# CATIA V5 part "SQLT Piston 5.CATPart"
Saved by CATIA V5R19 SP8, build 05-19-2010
Part number: SQLT Piston 5
Publications: "Droite.1", "Droite.2", "Plan.1", "Plan.2"
Bounding box of the stored display mesh (mm): x -1000 to 1000, y -1250 to 1200, z -750 to 3600
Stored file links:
  C:\Users\ThinkMotion\Desktop\EU_thinkMotion\iao\IAO_MMS_Groupe3\fovide\fovide\SQLT Piston 5.CATPart
  C:\Users\ThinkMotion\Desktop\EU_thinkMotion\iao\IAO_MMS_Groupe3\fovide\fovide\fovide.CATProduct
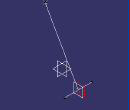
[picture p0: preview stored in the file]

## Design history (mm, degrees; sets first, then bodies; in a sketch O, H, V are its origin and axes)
External parameters (linked from other documents)
  `External.Diamètre bielle` = 150 mm
Set1
  Point1 "Point.E": linked copy from another document
  Point2 "Point.B": linked copy from another document
Set2 "set piston 5"
  Line1: type PtPt, FirstPoint Point1, SecondPoint Point2
  Line2: type Normal, RefPoint Point2, RefSkin yz-plane, Start -1000, End 1000
  Plane1: type OffsetPt, RefPlane yz-plane, RefPoint Point2
  Plane2: type Offset, RefPlane Plane1, Offset 150 {= `External.Diamètre bielle`}, reversed
Body1 (main body)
